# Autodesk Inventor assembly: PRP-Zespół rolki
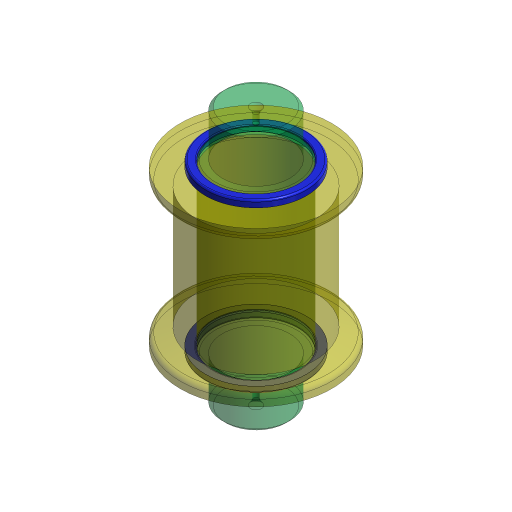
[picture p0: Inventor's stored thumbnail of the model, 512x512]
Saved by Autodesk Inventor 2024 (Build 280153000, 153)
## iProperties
Created: 2023-03
Part Number: PRP-Zespół rolki
Document SubType Name: Assembly
Designer: Andrzej Jaskulski
Mass: 60.2464 g
Surface Area: 198.901 cm^2
Volume: 60.2464 cm^3
Density: 1 g/cm^3
Checked By: A.J.
Engr Approved By: Andrzej Jaskulski
Mfg Approved By: Andrzej Jaskulski
Authority: A.J.
Company: ATC
Control State: 0
Master: False
Checked Out: False
Shininess: 20.0
Length Units: 11269
Angle Units: 11279
Time Units: 11290
Mass Units: 11283
Length Display Precision: 3
Angle Display Precision: 2
Compacted: True
Density: 0.0
Volumn: 0.0
Area: 0.0
PropertySet Name: Model Information
Title: A.J.: Kurs R2024-MEP
Author: Andrzej Jaskulski
Revision Number: 1/24
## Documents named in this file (4)
- C:\Users\AndJas\Documents\R2024-MEP\Obszar roboczy\PRP-Zespół rolki.iam
- C:\Users\AndJas\Documents\R2024-MEP\Obszar roboczy\PRP-Wałek.ipt
- C:\Users\AndJas\Documents\R2024-MEP\Obszar roboczy\PRP-Podkładka.ipt
- C:\Users\AndJas\Documents\R2024-MEP\Obszar roboczy\PRP-Rolka.ipt
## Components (4 placed, 3 different names)
1. S-PRP-Wałek:1 — Wstawiające:3
2. S-PRP-Podkładka:1 — Wstawiające:2, Wstawiające:3
3. S-PRP-Podkładka:2 — Wstawiające:1
4. S-PRP-Rolka:1 — Wstawiające:1, Wstawiające:2
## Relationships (3: Insert 3)
- Wstawiające:1 [Insert]: S-PRP-Podkładka:2 ↔ S-PRP-Rolka:1
- Wstawiające:2 [Insert]: S-PRP-Podkładka:1 ↔ S-PRP-Rolka:1
- Wstawiające:3 [Insert]: S-PRP-Wałek:1 ↔ S-PRP-Podkładka:1
